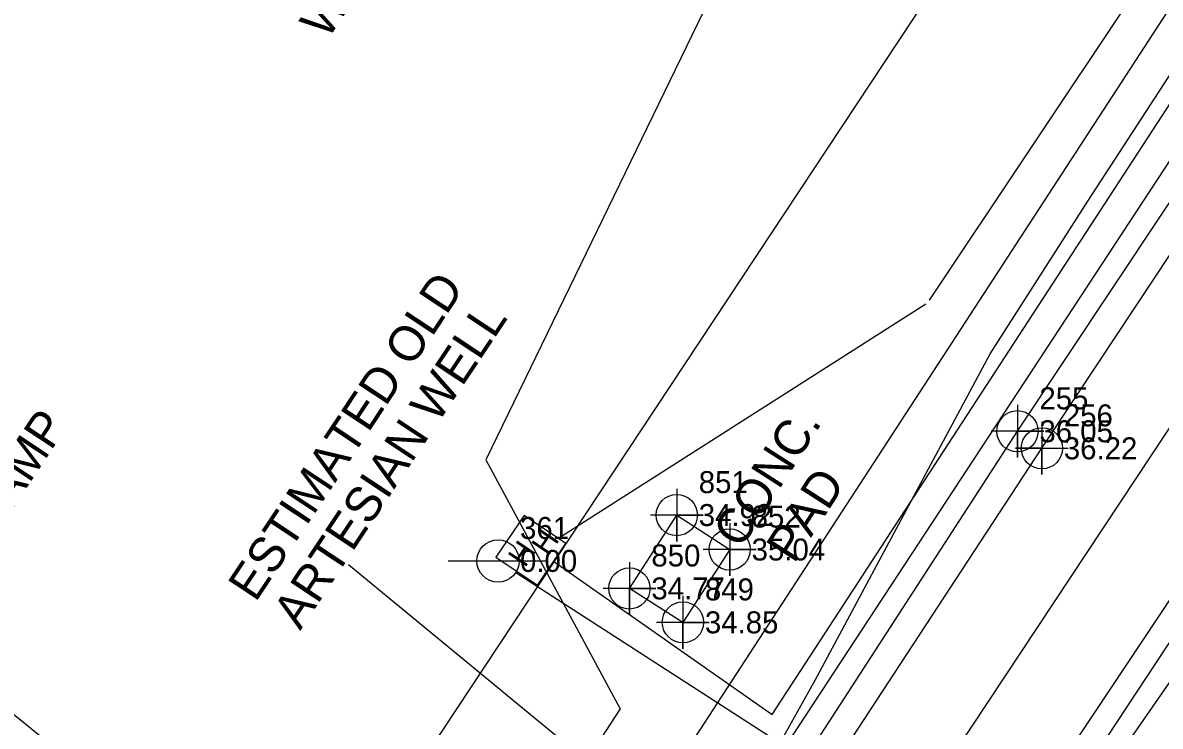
# Model space of a CAD drawing. Extents: x 2603627 to 2605187, y 896619 to 899063.
# Drawn here: x 2604493.2 to 2604622.7, y 898247.7 to 898327.7 of the extents above; entities that cross this region are included whole.
import ezdxf

# ---------------------------------------------------------------- set-up
doc = ezdxf.new("R2010")
doc.units = 0
for name, color, linetype in [('Exist Guardrail', 7, 'Continuous'), ('Exist Horizontal Alignment', 7, 'Continuous'), ('Exist Hydro Stream or Body of Water Text', 7, 'Continuous'), ('Exist Other Culture Area Outline Leader', 7, 'Continuous'), ('Exist Other Culture Area Outline Text', 7, 'Continuous'), ('Exist Right of Way Line', 7, 'Continuous'), ('Exist Roads EOP', 7, 'Continuous'), ('Exist Roads EOP Cogo Elevation', 7, 'Continuous'), ('Exist Roads EOP Cogo Number', 7, 'Continuous'), ('Exist Roads EOP Cogo Point CELL', 7, 'Continuous'), ('Exist Roads EOP Other', 7, 'Continuous'), ('Exist Roads EOP Other Cogo Elevation', 7, 'Continuous'), ('Exist Roads EOP Other Cogo Number', 7, 'Continuous'), ('Exist Roads EOP Other Cogo Point CELL', 7, 'Continuous'), ('Exist Roads EOP Other Text', 7, 'Continuous'), ('Exist Roads EOT', 7, 'Continuous'), ('Exist Roads EOT Cogo Elevation', 7, 'Continuous'), ('Exist Roads EOT Cogo Number', 7, 'Continuous'), ('Exist Roads EOT Cogo Point CELL', 7, 'Continuous'), ('Exist Utilities Telephone Hand Hole CELL', 7, 'Continuous'), ('Exist Utilities Telephone Pole CELL', 7, 'Continuous'), ('Exist Utilities Telephone Pole Cogo Elevation', 7, 'Continuous'), ('Exist Utilities Telephone Pole Cogo Number', 7, 'Continuous'), ('Exist Utilities Telephone UG Cable SUE LOS C', 7, 'Continuous'), ('Exist Utilities Telephone UG FO SUE LOS C', 7, 'Continuous'), ('Exist Vegetation Woods Line', 7, 'Continuous'), ('Exist Vegetation Woods Line Text', 7, 'Continuous')]:
    doc.layers.add(name, color=color, linetype=linetype)

# ---------------------------------------------------------------- blocks, each defined once
blk = doc.blocks.new('EXIST ROADS EOP COGO POINT')
at = {"layer": 'Exist Roads EOP Cogo Point CELL'}
blk.add_lwpolyline([(0, 0.06), (0, -0.06), (0, 0), (0.06, 0), (-0.06, 0)], dxfattribs=at)
blk.add_circle((0, 0), 0.0469, dxfattribs=at)
blk = doc.blocks.new('EXIST ROADS EOT COGO POINT')
at = {"layer": 'Exist Roads EOT Cogo Point CELL'}
blk.add_lwpolyline([(0, 0.06), (0, -0.06), (0, 0), (-0.06, 0), (0.06, 0)], dxfattribs=at)
blk.add_circle((0, 0), 0.0469, dxfattribs=at)
blk = doc.blocks.new('EXIST ROADS EOP OTHER COGO POINT')
at = {"layer": 'Exist Roads EOP Other Cogo Point CELL'}
blk.add_lwpolyline([(0, 0.06), (0, -0.06), (0, 0), (0.06, 0), (-0.06, 0)], dxfattribs=at)
blk.add_circle((0, 0), 0.0469, dxfattribs=at)

msp = doc.modelspace()

# ---------------------------------------------------------------- linework, layer by layer
at = {"layer": 'Exist Guardrail'}
for points in [[(2604549.45, 898197), (2604551.69, 898200.42), (2604561.03, 898214.38), (2604574.05, 898236.14), (2604583.44, 898252.9), (2604603.34, 898290.06), (2604614.45, 898307.44), (2604661.78, 898380.22)], [(2604631.98, 898264.56), (2604605.99, 898227.06), (2604595.34, 898211.26), (2604574.88, 898180.21)]]:
    msp.add_lwpolyline(points, dxfattribs=at)
at = {"layer": 'Exist Horizontal Alignment'}
msp.add_line((2604537.35, 898151.01), (2604647.76, 898317.92), dxfattribs=at)
at = {"layer": 'Exist Other Culture Area Outline Leader'}
msp.add_line((2604563.19, 898238.98), (2604530.32, 898266.04), dxfattribs=at)
at = {"layer": 'Exist Right of Way Line'}
msp.add_line((2604495.65, 898178.6), (2604606.06, 898345.5), dxfattribs=at)
at = {"layer": 'Exist Roads EOP'}
msp.add_line((2604600.14, 898221.38), (2604629.44, 898265.84), dxfattribs=at)
msp.add_lwpolyline([(2604577.96, 898237.27), (2604606.45, 898281.24), (2604633.89, 898322.5), (2604662.45, 898365.47), (2604690.62, 898408.06), (2604717.29, 898448.09), (2604745.46, 898490.11), (2604773.6, 898532.6), (2604800.88, 898573.95), (2604828.34, 898615.46), (2604855.1, 898656.15), (2604883.53, 898699.09), (2604911.29, 898740.95), (2604939.38, 898783.41), (2604966.33, 898824.04), (2604993.38, 898865.27), (2605022.2, 898908.38), (2605029.46, 898919.46)], dxfattribs=at)
at = {"layer": 'Exist Roads EOP Other'}
msp.add_lwpolyline([(2604568.38, 898259.49), (2604562.29, 898263.35), (2604567.68, 898271.7), (2604573.7, 898267.78), (2604568.38, 898259.49)], dxfattribs=at)
at = {"layer": 'Exist Roads EOT'}
for points in [[(2604580.65, 898235.67), (2604609.23, 898279.3), (2604636.66, 898320.72), (2604665.18, 898363.91), (2604693.37, 898406.36), (2604719.95, 898446.05), (2604748, 898488.34), (2604776.15, 898530.84), (2604803.5, 898572.3), (2604830.95, 898613.91), (2604857.58, 898654.47), (2604886.02, 898697.38), (2604913.86, 898739.33), (2604942.03, 898781.72), (2604969.06, 898822.38), (2604996.07, 898863.44), (2605024.73, 898906.73), (2605032, 898917.78)], [(2604598.04, 898223.4), (2604627.23, 898267.23), (2604654.64, 898308.57), (2604683.28, 898352.01), (2604711.27, 898394.14), (2604737.98, 898434.05), (2604766.04, 898475.94), (2604794.96, 898519.26), (2604821.61, 898559.82), (2604848.89, 898601.4), (2604876.12, 898642.73), (2604904.4, 898685.35), (2604932.33, 898727.23), (2604960.29, 898769.49), (2604987.32, 898810.19), (2605014.12, 898850.95), (2605043.08, 898894.89), (2605050.2, 898905.72)]]:
    msp.add_lwpolyline(points, dxfattribs=at)
at = {"layer": 'Exist Utilities Telephone Hand Hole CELL'}
for p, q in [((2604550.31, 898271.66), (2604547.1, 898266.92)), ((2604555.05, 898268.45), (2604550.31, 898271.66)), ((2604551.84, 898263.71), (2604555.05, 898268.45)), ((2604547.1, 898266.92), (2604551.84, 898263.71)), ((2604551.07, 898267.68), (2604551.07, 898267.68))]:
    msp.add_line(p, q, dxfattribs=at)
at = {"layer": 'Exist Utilities Telephone Pole CELL'}
for p, q in [((2604541.66, 898266.48), (2604553, 898266.48)), ((2604547.34, 898266.48), (2604547.34, 898266.48))]:
    msp.add_line(p, q, dxfattribs=at)
msp.add_circle((2604547.34, 898266.48), 2.41, dxfattribs=at)
at = {"layer": 'Exist Utilities Telephone UG Cable SUE LOS C'}
for p, q in [((2604580.04, 898245.37), (2604795.48, 898573.63)), ((2604596.46, 898296.17), (2604658.71, 898389.49)), ((2604554.16, 898269.05), (2604596.02, 898295.74)), ((2604549.35, 898265.16), (2604580.04, 898245.37))]:
    msp.add_line(p, q, dxfattribs=at)
at = {"layer": 'Exist Utilities Telephone UG FO SUE LOS C'}
for p, q in [((2604555.47, 898224.4), (2604671.2, 898402.26)), ((2604578.55, 898248.99), (2604676.14, 898398.98)), ((2604553.68, 898266.42), (2604578.55, 898248.99))]:
    msp.add_line(p, q, dxfattribs=at)
at = {"layer": 'Exist Vegetation Woods Line'}
msp.add_lwpolyline([(2604591.9, 898412.36), (2604622.51, 898404.04), (2604578.27, 898344.62), (2604545.93, 898277.97), (2604561.25, 898249.64), (2604543.06, 898221.77), (2604504.96, 898238.63), (2604486.58, 898253.52)], dxfattribs=at)

# ---------------------------------------------------------------- block references
at = {"layer": 'Exist Roads EOP Cogo Point CELL', "xscale": 50, "yscale": 50}
msp.add_blockref('EXIST ROADS EOP COGO POINT', (2604606.45, 898281.24), dxfattribs=at)
at = {"layer": 'Exist Roads EOP Other Cogo Point CELL', "xscale": 50, "yscale": 50}
for p in [(2604567.68, 898271.7), (2604573.7, 898267.78), (2604562.29, 898263.35), (2604568.38, 898259.49)]:
    msp.add_blockref('EXIST ROADS EOP OTHER COGO POINT', p, dxfattribs=at)
at = {"layer": 'Exist Roads EOT Cogo Point CELL', "xscale": 50, "yscale": 50}
msp.add_blockref('EXIST ROADS EOT COGO POINT', (2604609.23, 898279.3), dxfattribs=at)

# ---------------------------------------------------------------- texts
at = {"layer": 'Exist Hydro Stream or Body of Water Text'}
msp.add_text('QUICCOSION SWAMP', height=4, rotation=56.4094, dxfattribs=at).set_placement((2604467.36, 898235.13))
at = {"layer": 'Exist Other Culture Area Outline Text'}
for s, p in [('ESTIMATED OLD ', (2604519.74, 898261.68)), ('ARTESIAN WELL', (2604524.82, 898258.49))]:
    msp.add_text(s, height=4, rotation=56.4094, dxfattribs=at).set_placement(p)
at = {"layer": 'Exist Roads EOP Cogo Elevation'}
msp.add_text('36.05', height=2.5, dxfattribs=at).set_placement((2604608.95, 898279.99))
at = {"layer": 'Exist Roads EOP Cogo Number'}
msp.add_text('255', height=2.5, dxfattribs=at).set_placement((2604608.95, 898283.74))
at = {"layer": 'Exist Roads EOP Other Cogo Elevation'}
for s, p in [('34.92', (2604570.18, 898270.45)), ('35.04', (2604576.2, 898266.53)), ('34.77', (2604564.79, 898262.1)), ('34.85', (2604570.88, 898258.24))]:
    msp.add_text(s, height=2.5, dxfattribs=at).set_placement(p)
at = {"layer": 'Exist Roads EOP Other Cogo Number'}
for s, p in [('851', (2604570.18, 898274.2)), ('852', (2604576.2, 898270.28)), ('850', (2604564.79, 898265.85)), ('849', (2604570.88, 898261.99))]:
    msp.add_text(s, height=2.5, dxfattribs=at).set_placement(p)
at = {"layer": 'Exist Roads EOP Other Text'}
for s, p in [('CONC.', (2604574.96, 898267.74)), ('PAD', (2604581.02, 898266.08))]:
    msp.add_text(s, height=4, rotation=57.3037, dxfattribs=at).set_placement(p)
at = {"layer": 'Exist Roads EOT Cogo Elevation'}
msp.add_text('36.22', height=2.5, dxfattribs=at).set_placement((2604611.73, 898278.05))
at = {"layer": 'Exist Roads EOT Cogo Number'}
msp.add_text('256', height=2.5, dxfattribs=at).set_placement((2604611.73, 898281.8))
at = {"layer": 'Exist Utilities Telephone Hand Hole CELL'}
for p in [(2604553.05, 898266.93), (2604550.4, 898265.63)]:
    msp.add_text('H', height=2.5, rotation=55.8889, dxfattribs=at).set_placement(p)
at = {"layer": 'Exist Utilities Telephone Pole Cogo Elevation'}
msp.add_text('0.00', height=2.5, dxfattribs=at).set_placement((2604549.84, 898265.23))
at = {"layer": 'Exist Utilities Telephone Pole Cogo Number'}
msp.add_text('361', height=2.5, dxfattribs=at).set_placement((2604549.84, 898268.98))
at = {"layer": 'Exist Vegetation Woods Line Text'}
msp.add_text('WOODS', height=4, rotation=56.4786, dxfattribs=at).set_placement((2604527.92, 898325.7))

doc.saveas('drawing.dxf')
